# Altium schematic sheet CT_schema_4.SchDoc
size 283 x 169 mm
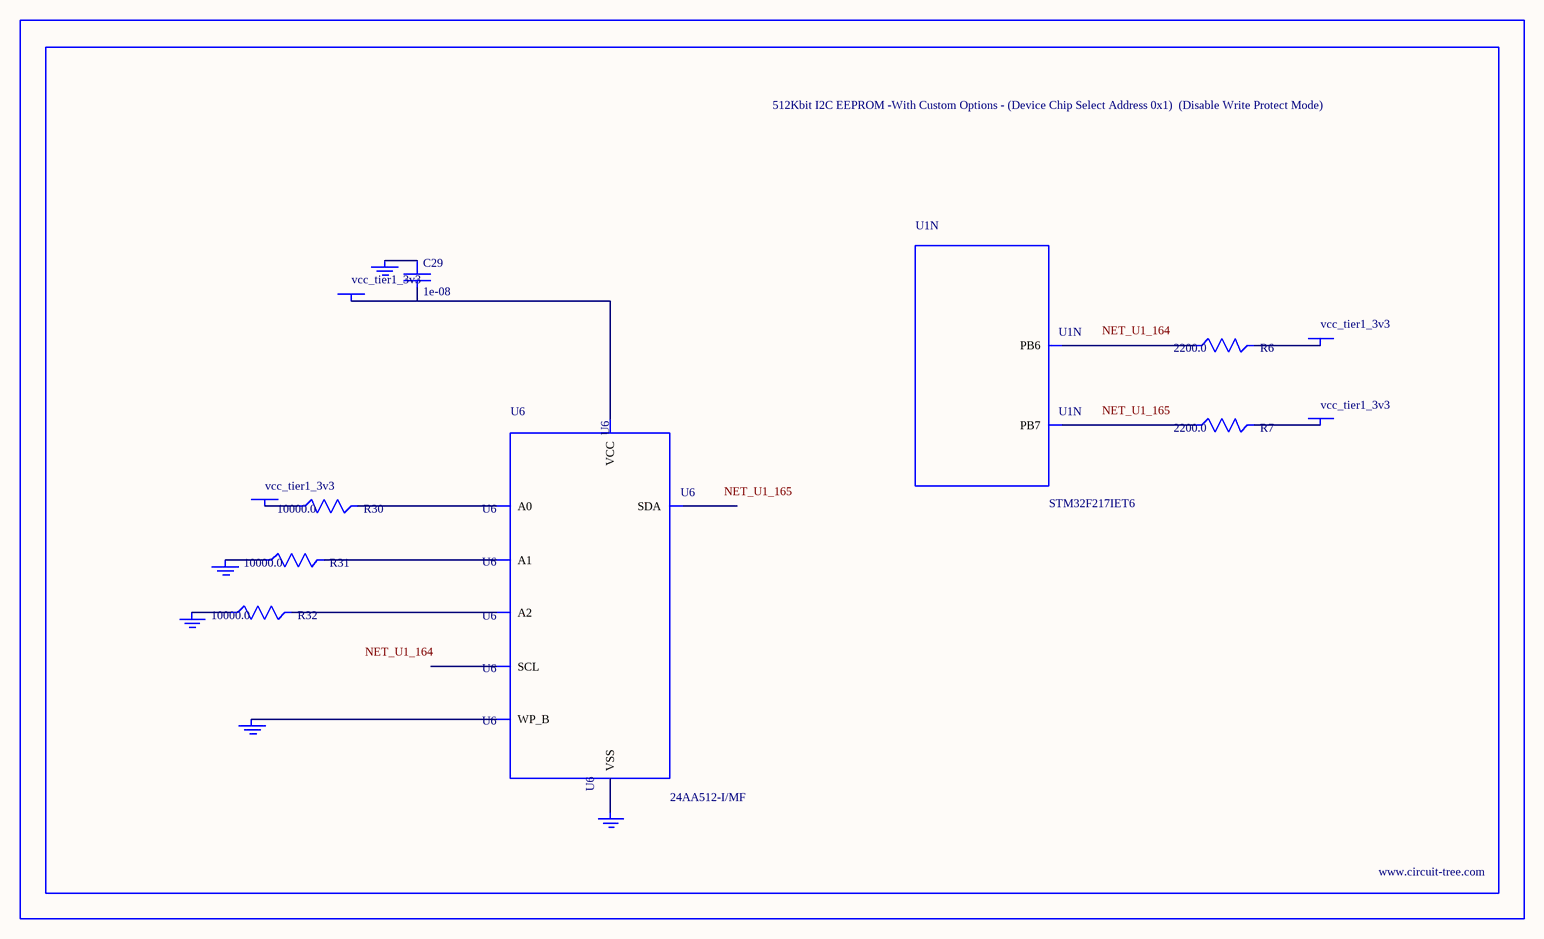
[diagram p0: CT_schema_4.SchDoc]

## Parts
BORDER3  (no value)
C29  1e-08  [C0402]
GND_INSTANCE_3_0  (no value)
GND_INSTANCE_3_1  (no value)
GND_INSTANCE_3_2  (no value)
GND_INSTANCE_3_3  (no value)
GND_INSTANCE_3_4  (no value)
POWER_INSTANCE_3_0  vcc_tier1_3v3
POWER_INSTANCE_3_1  vcc_tier1_3v3
POWER_INSTANCE_3_2  vcc_tier1_3v3
POWER_INSTANCE_3_3  vcc_tier1_3v3
R6  2200.0  [R0603]
R7  2200.0  [R0603]
R30  10000.0  [R0603]
R31  10000.0  [R0603]
R32  10000.0  [R0603]
U1  STM32F217IET6  [LQFP176]  (part N of 14)
U6  24AA512-I/MF  [DFN8-S]

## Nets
NetC29_1: C29.1 GND_INSTANCE_3_3.0(GND)
NetC29_2: C29.2 POWER_INSTANCE_3_1.0(PWR) U6.8(VCC)
NetGND_INSTANCE_3_0_0: GND_INSTANCE_3_0.0(GND) R31.1
NetGND_INSTANCE_3_1_0: GND_INSTANCE_3_1.0(GND) R32.1
NetGND_INSTANCE_3_2_0: GND_INSTANCE_3_2.0(GND) U6.7(WP_B)
NetGND_INSTANCE_3_4_0: GND_INSTANCE_3_4.0(GND) U6.4(VSS)
NetPOWER_INSTANCE_3_0_0: POWER_INSTANCE_3_0.0(PWR) R30.1
NetPOWER_INSTANCE_3_2_0: POWER_INSTANCE_3_2.0(PWR) R6.2
NetPOWER_INSTANCE_3_3_0: POWER_INSTANCE_3_3.0(PWR) R7.2
NetR6_1: R6.1 U1.164(PB6)
NetR7_1: R7.1 U1.165(PB7)
NetR30_2: R30.2 U6.1(A0)
NetR31_2: R31.2 U6.2(A1)
NetR32_2: R32.2 U6.3(A2)

Not connected (* = marked no-connect by the designer): U6 5(SDA) 6(SCL)

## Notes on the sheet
- Labels drawn without touching a wire or pin: NET_U1_164, NET_U1_165

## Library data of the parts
BORDER3 = BORDER_PAGE3
C29 = C0402C103K3RAC
GND_INSTANCE_3_0-GND_INSTANCE_3_4 = GND
POWER_INSTANCE_3_0-POWER_INSTANCE_3_3 = PWR
R6 R7 = RC0603JR-072K2L
R30-R32 = RC0603JR-0710KL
